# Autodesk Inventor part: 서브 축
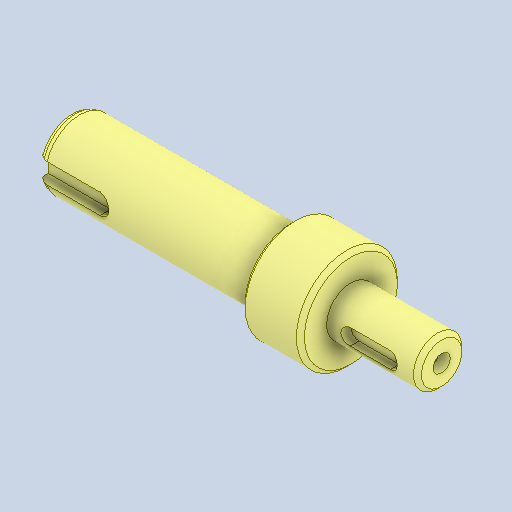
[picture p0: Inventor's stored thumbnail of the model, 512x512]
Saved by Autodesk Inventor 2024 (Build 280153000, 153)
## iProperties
Created: 2026-07
Part Number: 서브 축
Material: 강철, 탄소
Document SubType Name: Modeling
Designer: com
Density: 7.85 g/cm^3
Appearance: 기본값
Author: jhkim
Revision Number: 1
Sending System: Autodesk Inventor 2027
Preprocessor: ST-DEVELOPER v20.1
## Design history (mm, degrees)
node "서브 축1"
node "솔리드2"
node "솔리드1"
